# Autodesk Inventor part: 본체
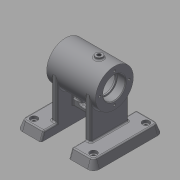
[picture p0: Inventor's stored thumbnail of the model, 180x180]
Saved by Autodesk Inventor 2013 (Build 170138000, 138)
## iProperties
Created: 2016-07
Part Number: 본체
Material: 일반
Document SubType Name: Modeling
Designer: Administrator
Density: 1 g/cm^3
Author: Administrator
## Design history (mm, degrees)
sketch "스케치1"
  geometry: L1 (0, 0)-(0, 70); C1 r 27 at (0, 70); 1 further point
  constraints: 2 coincident, 2 end point, 1 centre point, 1 vertical
  dimensions: "d0" = 54 diameter of C1; "d15" = 70 distance of L1.start L1.end
extrude "돌출1" new body sketch "스케치1" stored distance "d2" = 70; taper "d3" = 0 deg
sketch "스케치2"
  geometry: L1 (-35, 97)-(-35, 43) reference; L2 (35, 43)-(35, 97) reference; L3 (-35, 86)-(-23, 86); L4 (-23, 86)-(-23, 84); L5 (-23, 84)-(-21, 84); L6 (-21, 84)-(-21, 92); L7 (-21, 92)-(21, 92); L8 (21, 92)-(21, 84); L9 (21, 84)-(23, 84); L10 (23, 84)-(23, 86); L11 (23, 86)-(35, 86); L12 (-35, 70)-(35, 70); 1 further point
  constraints: 20 end point, 5 perpendicular, 4 parallel, 2 midpoint, 2 point on line
  dimensions: "d4" = 32 diameter of L3 L12; "d6" = 28 diameter of L5 L12; "d7" = 44 diameter of L7 L12; "d8" = 28 diameter of L9 L12; "d9" = 32 diameter of L11 L12; "d10" = 12 distance of L3.start L3.end; "d11" = 42 distance of L6.end L7.end; "d12" = 12 distance of L10.end L11.end; "d13" = 2 distance of L8.end L9.end
revolve "회전1" sketch "스케치2" stored, may be unused: angle "d14" = 90 deg
sketch "스케치3"
  geometry: L1 (-55, -50)-(-20, -50); L2 (-20, -50)-(-20, 50); L3 (-20, 50)-(-55, 50); L4 (-55, 50)-(-55, -50); L5 (0, 0)-(-72.5, 0)
  constraints: 10 end point, 2 parallel, 2 perpendicular, 1 horizontal, 1 other
  dimensions: "d16" = 35 distance of L2.end L3.end; "d18" = 100 distance of L3.end L1.start; "d37" = 55 distance from line of L4 L5.start
extrude "돌출2" join sketch "스케치3" distance "d20" = 12; taper "d21" = 0 deg
feature "면 기울기1" dims angle "d22" = -20 deg
fillet "모깎기3" dims "d26" = 10, "d27" = 5, "d28" = 10, "d29" = 5
sketch "스케치5"
  geometry: L1 (-50.632, 41.41)-(-50.632, -41.41) reference; L2 (-46.41, -45.632)-(-20, -45.632) reference; L3 (-20, -45.632)-(-20, 45.632) reference; L4 (-20, 45.632)-(-46.41, 45.632) reference; L5 (-42.5, -37.5)-(-42.5, 37.5); L6 (-42.5, 0)-(0, 0); 5 further points; 2 other entities
  constraints: 4 end point, 3 coincident, 2 perpendicular, 1 midpoint, 2 other
  dimensions: "d34" = 75 distance of L5.start L5.end; "d36" = 42.5 distance from line of L5 point (0, 0)
hole "구멍1" sketch "스케치5" at (-42.5, -37.5), (-42.5, 37.5) diameter "d38" = 6; stored, may be unused: countersink angle "d42" = 90 deg, drill point angle "d44" = 118 deg; dims "d39" = 6, "d40" = 10, "d41" = 4, "d43" = 8
sketch "스케치6"
  geometry: L1 (-12, 4.368)-(-12, 95.632) reference; L2 (0, 50)-(-70, 50); L3 (-12, 23)-(-70, 23); L4 (-12, 77)-(-70, 77); A1 r 27 centre (-70, 50) between (-70, 23) and (-70, 77) reference
  constraints: 6 end point, 2 parallel, 2 point on circle, 2 point on line, 1 perpendicular, 1 other
  dimensions: "d45" = 54 distance between parallel lines of L4 L3
extrude "돌출3" join sketch "스케치6" distance "d46" = 8; taper "d47" = 0 deg
fillet "모깎기4" dims "d48" = 2
fillet "모깎기5" dims "d49" = 2
sketch "스케치7"
  geometry: L1 (-15.325, 22)-(15.005, 22); L2 (35, 43)-(-35, 43) reference; 1 further point
  constraints: 2 end point, 1 horizontal
  dimensions: "d50" = 21 distance between parallel lines of L1 L2
feature "리브1" sketch "스케치7" dims "d51" = 1, "d52" = 8, "d53" = 0, "d54" = 0, "d55" = 1, "d56" = 1
sketch "스케치8"
  geometry: L1 (28, 13.5)-(12, 13.5); L2 (12, 6.5)-(28, 6.5); L3 (12, 10)-(28, 10); L4 (66.555, -22)-(42, -22) reference; L5 (20, -22)-(20, 17.838); A1 r 3.5 centre (12, 10) between (12, 13.5) and (12, 6.5); A2 r 3.5 centre (28, 10) between (28, 6.5) and (28, 13.5)
  constraints: 8 end point, 4 point on circle, 4 tangent, 2 centre point, 2 parallel, 1 horizontal, 1 perpendicular
  dimensions: "d57" = 3.5 radius of A2; "d59" = 23 dimension on A2 A1; "d60" = 32 distance between parallel lines of L3 L4; "d61" = 11.5 dimension on A1 L5
extrude "돌출4" cut sketch "스케치8" stored distance "d62" = 8; taper "d63" = 0 deg
fillet "모깎기6" dims "d64" = 2
fillet "모깎기7" dims "d65" = 2
node "작업 평면2"
  node "작업 평면1"
sketch "스케치9"
  geometry: L1 (-35, 27)-(-35, -27) reference; L2 (-35, 0)-(13, 0); C1 r 5 at (13, 0); 1 further point
  constraints: 2 end point, 1 centre point, 1 coincident, 1 midpoint, 1 perpendicular
  dimensions: "d67" = 48 distance of L2.start L2.end; "d69" = 10 diameter of C1
extrude "돌출5" join sketch "스케치9" stored distance "d70" = 8; taper "d71" = 0 deg
hole "구멍2" diameter "d74" = 5.188; stored, may be unused: countersink angle "d78" = 90 deg, drill point angle "d80" = 118 deg; dims "d72" = 10, "d73" = 10, "d75" = 6, "d76" = 10, "d77" = 4, "d79" = 8
sketch "스케치10"
  geometry: L1 (0, 70)-(0, 51.416); L2 (0, 70)-(-15.898, 44.559); C1 r 14 at (0, 70) reference; 1 further point
  constraints: 4 end point, 1 vertical
  dimensions: "d83" = 30 distance of L1.start L2.end; "d122" = 32 deg angle of L1 L2
node "작업 평면3"
sketch "스케치11"
  geometry: C1 r 6 at (0, 0); 2 further points
  constraints: 1 centre point, 1 coincident
  dimensions: "d84" = 12 diameter of C1
extrude "돌출6" join sketch "스케치11" stored distance "d86" = 8; taper "d87" = 0 deg
hole "구멍3" diameter "d90" = 5.188; stored, may be unused: countersink angle "d94" = 90 deg, drill point angle "d96" = 118 deg; dims "d88" = 10, "d89" = 10, "d91" = 6, "d92" = 10, "d93" = 4, "d95" = 8
fillet "모깎기9" dims "d97" = 2
sketch "스케치12" dims "d98" = 42
  geometry: L1 (0, 0)-(-21, 0); C1 r 27 at (0, 0) reference; 2 further points
  constraints: 2 coincident, 2 end point, 1 horizontal, 1 horizontal alignment, 2 other
hole "구멍4" sketch "스케치12" at (-21, 0) diameter "d100" = 3.242; stored, may be unused: countersink angle "d104" = 90 deg, drill point angle "d106" = 118 deg; dims "d101" = 8, "d102" = 10, "d103" = 4, "d105" = 10
chamfer "모따기1" distance "d110" = 1; stored, may be unused: second distance "d111" = 2, angle "d112" = 45 deg
fillet "모깎기10" dims "d113" = 0.3, "d114" = 3
node "작업 평면5"
sketch "스케치14"
  geometry: L1 (-24.43, 73.457)-(24.43, 73.457); L2 (24.43, 73.457)-(24.43, 66.543); L3 (24.43, 66.543)-(-24.43, 66.543); L4 (-24.43, 66.543)-(-24.43, 73.457); L5 (-24.43, 73.457)-(24.43, 66.543); L6 (-35, 97)-(-35, 43) reference; L7 (35, 43)-(35, 97) reference; L8 (-35, 70)-(35, 70); 2 further points
  constraints: 4 end point, 4 midpoint, 2 other
feature "엠보싱2" sketch "스케치14" dims "d120" = 0.5, "d121" = 0
node "솔리드1"
mirror "대칭1"
pattern_circular "원형 패턴1" dims angle "d108" = 360 deg
mirror "대칭2"
node "투영된 루프1"
other parameters: "d66" = 3
